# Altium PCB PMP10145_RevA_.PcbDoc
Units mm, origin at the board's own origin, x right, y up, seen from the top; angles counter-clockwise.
Board outline 111 x 62 mm, 2 copper layers (Top Layer, Bottom Layer), stack 1.57 mm thick; 72 components, 120 nets, 175 pads, 38 vias.
Unrouted connection lines stored in the file: 1.
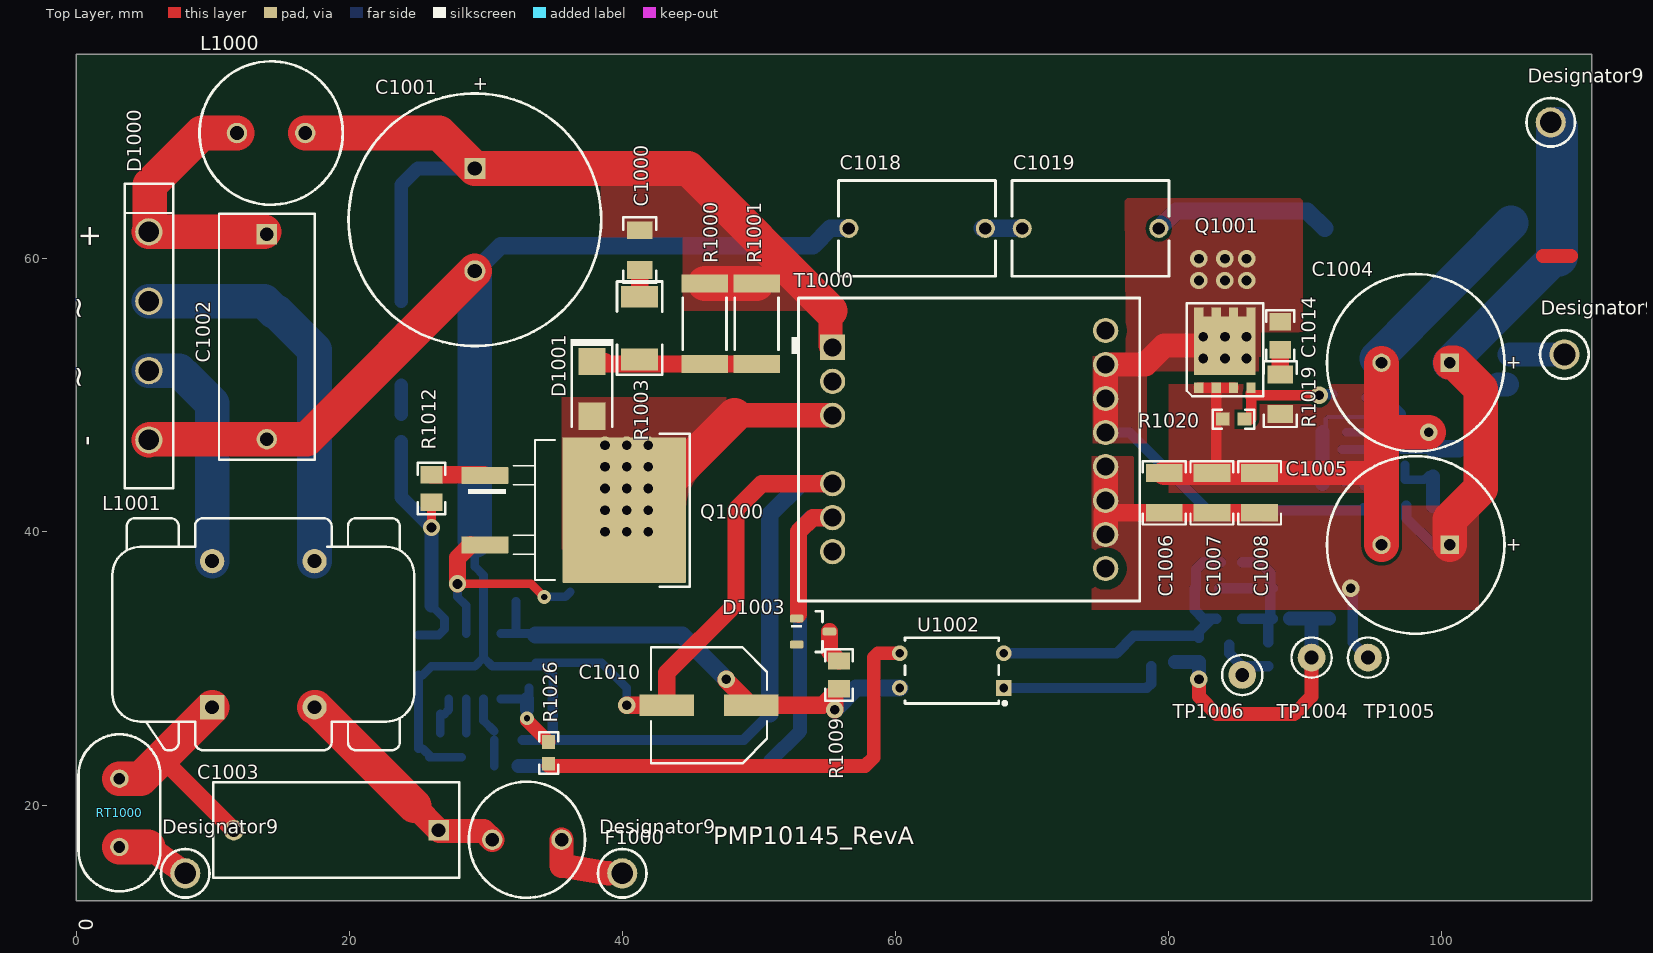
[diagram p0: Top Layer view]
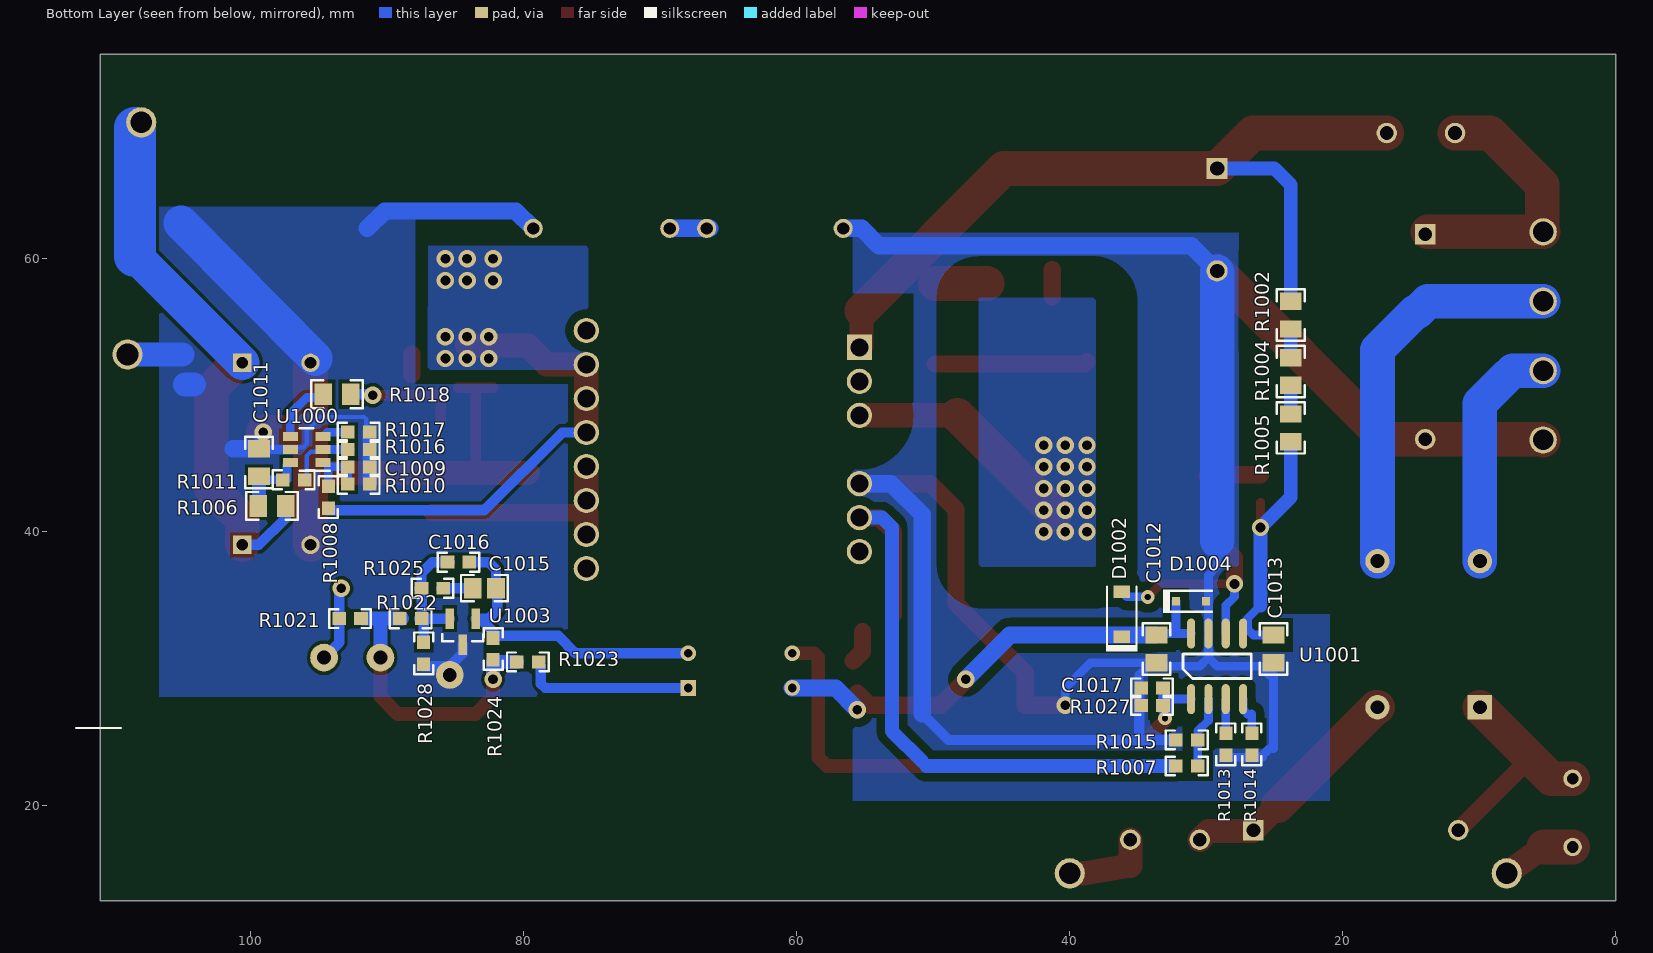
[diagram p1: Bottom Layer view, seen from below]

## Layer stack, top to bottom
Top Solder: solder mask 0.01, Solder Resist, Dk 3.5
Top Layer: signal copper 0.035
Dielectric 1: core 1.5, FR-4, Dk 4.2
Bottom Layer: signal copper 0.035
Bottom Solder: solder mask 0.01, Solder Resist, Dk 3.5

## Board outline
0,13 111,13 111,75 0,75

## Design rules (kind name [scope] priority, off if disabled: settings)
AssemblyTestPointUsage [All] p1 off:
AssemblyTestpoint [All] p1 off: testpointundercomponent=TRUE minsize=1.016 maxsize=2.54 preferedsize=1.524 minholesize=0 maxholesize=1.016 preferedholesize=0.813 testpointgrid=0.025 usegrid=TRUE gridtolerance=0 allowsidetop=TRUE allowsidebottom=TRUE
Clearance "PGND C1000" [InNet('PGND') vs InNet('NetC1000_1')] p1: gap=3.048
Clearance "PGND D1001" [InNet('PGND') vs InNet('NetD1001_2')] p2: gap=3.048
Clearance GND [InNet('GND')] p3: gap=0.254
Clearance "N L1" [InNet('V_N') vs InNet('V_L1')] p4: gap=3.048
Clearance Clearance_polygon [INPOLYGON] p5: gap=0.635
Clearance "PGND Vin" [InNet('PGND') vs InNet('NetC1000_1')] p6: gap=3.048
Clearance "PGND ALL" [InNet('PGND')] p7: gap=0.635
DiffPairsRouting [All] p1: maxlimit=0.254 minlimit=0.254 mostfreqgap=0.254 toplayer_minwidth=0.254 toplayer_maxwidth=3.048 toplayer_prefwidth=0.381 bottomlayer_minwidth=0.254 bottomlayer_maxwidth=3.048 bottomlayer_prefwidth=0.381 maxuncoupledlength=12.7
FabricationTestPointUsage [All] p1 off: valid=0 allowmultiple=FALSE
FabricationTestpoint [All] p1 off: side=3 testpointundercomponent=TRUE minsize=1.016 maxsize=2.54 preferedsize=1.524 minholesize=0 maxholesize=1.016 preferedholesize=0.813 testpointgrid=0.025 allowsidetop=TRUE allowsidebottom=TRUE usegrid=TRUE gridtolerance=0
Height [All] p1: minheight=0 maxheight=50.8 prefheight=12.7
HoleSize [All] p1: absolutevalues=TRUE maxlimit=25.4 minlimit=0.025 maxpercent=80.000 minpercent=20.000
MinimumSolderMaskSliver [All] p1: minsoldermaskwidth=0.025
PasteMaskExpansion [All] p1: expansion=-0.025
PlaneClearance [All] p1: clearance=0.279
PlaneConnect [All] p1: planeconnectstyle=Relief reliefexpansion=0.152 reliefentries=4 reliefconductorwidth=0.254 reliefairgap=0.178
PolygonConnect PolygonConnect_VIA [ISVIA] p1: connectstyle=Direct reliefconductorwidth=0.254 reliefentries=4 polygonreliefangle="90 Angle" airgapwidth=0.254
PolygonConnect [All] p2: connectstyle=Direct reliefconductorwidth=0.254 reliefentries=4 polygonreliefangle="90 Angle" airgapwidth=0.254
RoomDefinition V3 [InComponentClass('V3')] p1: confinementstyle=ConfineIn formatcopy=TRUE lockcomponents=FALSE outline -255.27,-245.872 -204.47,-245.872 -204.47,-220.472 -255.27,-220.472
RoutingVias [All] p1: holewidth=0.4 width=0.705 viastyle="Through Hole" minholewidth=0.2 minwidth=0.505 maxholewidth=1 maxwidth=1.991
SilkToBoardRegionClearance [All] p1 off:
SilkToSilkClearance [All] p1: silktosilkclearance=0.102
SilkToSolderMaskClearance SilkscreenOverComponentPads [IsPad] p1: minsilkscreentomaskgap=0.051 clearancetoexposedcopper=TRUE
SolderMaskExpansion SolderMaskExpansion_qfn48 [HasFootprint('QFN48#0.5')] p1: expansion=0.051
SolderMaskExpansion SolderMaskExpansion_32QN2 [(HasFootprint('32QN2'))] p2: expansion=0.051
SolderMaskExpansion [All] p3: expansion=0.051
UnpouredPolygon [All] p1: allowunpoured=FALSE
Width Width_ekran [InNet('GND')] p1: maxlimit=3.048 minlimit=0.127 preferedwidth=0.254
Width [All] p2: maxlimit=3.048 minlimit=0.127 preferedwidth=0.254
15 further rules are at their usual default settings.

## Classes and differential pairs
net class V_L[3..1]: V_L1 V_L2 V_L3
channel class V_PHASE_IN: V1 V2 V3
channel class I_CT_IN: I1 I2 I3 I4
net class V_PAHSE[3..1]: V_PAHSE1 V_PAHSE2 V_PAHSE3
net class I_CT_P[4..1]: I_CT_P1 I_CT_P2 I_CT_P3 I_CT_P4
net class I_CT_N[4..1]: I_CT_N1 I_CT_N2 I_CT_N3 I_CT_N4
component class Main: C20 TP8 TP12 U4
differential pair RS1: +RS1_P -RS1_N
differential pair RS: +RS_P -RS_N

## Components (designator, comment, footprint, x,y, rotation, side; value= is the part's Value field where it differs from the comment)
C1000 "C3216X7R2J472K" 1206 41.275,60.642 r270 top
C1001 "EKXG451ELL680MMN3S" KXG_1800x3150 29.21,62.865 r270 top
C1002 "B32922C3224K" B32922_12.5mm 13.97,54.292 r270 top
C1003 "B32922C3224K" B32922_12.5mm 19.05,18.161 r180 top
C1004 "EKZE350ELL681MK20S" KZE_1250x2000 98.108,52.387 r180 top
C1005 "EKZE350ELL681MK20S" KZE_1250x2000 98.108,39.052 r180 top
C1006 "GRM32ER71C226ME18L" 1210 79.692,42.862 r90 top
C1007 "GRM32ER71C226ME18L" 1210 83.185,42.862 r90 top
C1008 "GRM32ER71C226ME18L" 1210 86.677,42.862 r90 top
C1009 "Used in BOM report" 0603 92.075,44.767 r180 bottom
C1010 "EEE-FC1V470P" SM_RADIAL_E 46.355,27.305 r180 top
C1011 "GRM219R71E105KA88D" 0805_HV 99.377,45.085 r90 bottom
C1012 "08055C104JAT2A" 0805_HV 33.655,31.432 r270 bottom
C1013 "08055C104JAT2A" 0805_HV 25.082,31.432 r270 bottom
C1014 "GRM2165C2A222JA01D" 0805_HV 88.186,54.372 r270 top
C1015 "Used in BOM report" 0805 82.867,35.877 r180 bottom
C1016 "C0603C103J5RACTU" 0603 84.772,37.782 r180 bottom
C1017 "06035A101JAT2A" 0603 33.972,28.575 r0 bottom
C1018 "ECKANA222ME" CD_1150x700x1550 61.595,62.23 r180 top
C1019 "ECKANA222ME" CD_1150x700x1550 74.295,62.23 r180 top
D1000 "GBU4J" GBU 5.334,54.356 r270 top
D1001 "MURA160T3G" SMA 37.782,50.482 r270 top
D1002 "MBR0540T1G" SOD-123 36.195,33.972 r90 bottom
D1003 "BAS21-7-F" SOT-23 53.975,32.703 r0 top
D1004 "MMSZ5251BS-7-F" sod-323 31.115,34.925 r180 bottom
Designator9 "Comment" Keystone5011 109,53 r0 top
Designator9 "Comment" Keystone5010 108,70 r0 top
Designator9 "Comment" Keystone5010 8,15 r0 top
Designator9 "Comment" Keystone5010 40,15 r0 top
F1000 "37212000001" FUSE_372 33.02,17.462 r0 top
L1000 "7447480331" WE_TI_1014 14.287,69.215 r0 top
L1001 "744823210" IND_WE-CMB_M 13.716,32.512 r90 top
Q1000 "STB8N65M5" DDPAK 36.195,41.593 r0 top
Q1001 "CSD19531Q5A" TRANS_NexFET_Q5A 84.138,53.34 r90 top
R1000 "CRCW2512100KJNEG" 2512 46.038,55.245 r90 top
R1001 "CRCW2512100KJNEG" 2512 49.847,55.245 r90 top
R1002 "CRCW08051M00FKEA" 0805_HV 23.812,55.88 r90 bottom
R1003 "CRCW201047R0JNEF" 2010 41.275,54.927 r90 top
R1004 "CRCW08051M00FKEA" 0805_HV 23.812,51.752 r90 bottom
R1005 "CRCW08051M00FKEA" 0805_HV 23.812,47.625 r90 bottom
R1006 "CRCW080510R0JNEA" 0805_HV 98.425,41.91 r180 bottom
R1007 "CRCW0603191KFKEA" 0603 31.432,22.86 r0 bottom
R1008 "Used in BOM report" 0603 94.297,42.545 r90 bottom
R1009 "CRCW080510R0JNEA" 0805_HV 55.88,29.527 r90 top
R1010 "Used in BOM report" 0603 92.075,43.497 r0 bottom
R1011 "Used in BOM report" 0603 96.837,43.815 r0 bottom
R1012 "CRCW080510R0JNEA" 0805_HV 26.035,43.18 r270 top
R1013 "CRCW060333K2FKEA" 0603 28.575,24.447 r90 bottom
R1014 "CRCW0603100KFKEA" 0603 26.67,24.447 r90 bottom
R1015 "CRCW060356K2FKEA" 0603 31.432,24.765 r180 bottom
R1016 "Used in BOM report" 0603 92.075,46.038 r0 bottom
R1017 "Used in BOM report" 0603 92.075,47.307 r0 bottom
R1018 "CRCW080510R0JNEA" 0805_HV 93.662,50.086 r180 bottom
R1019 "CRCW120610R0JNEA" 1206 88.186,50.086 r90 top
R1020 "Used in BOM report" 0603 84.772,48.26 r0 top
R1021 "CRCW060349R9FKEA" 0603 92.71,33.655 r180 bottom
R1022 "CRCW0603100KFKEA" 0603 88.265,33.655 r0 bottom
R1023 "CRCW06031K00FKEA" 0603 79.692,30.48 r0 bottom
R1024 "CRCW06034K99FKEA" 0603 82.233,31.432 r270 bottom
R1025 "Used in BOM report" 0603 86.677,35.877 r0 bottom
R1026 "CRCW060320K0FKEA" 0603 34.608,23.812 r270 top
R1027 "CRCW0603100KFKEA" 0603 33.972,27.305 r180 bottom
R1028 "CRCW060338K3FKEA" 0603 87.312,31.115 r90 bottom
RT1000 "B57236S0100M000" THERM_B57236S0 3.175,19.431 r90 top
T1000 "750315431" Wurth_750315431 65.405,46.038 r0 top
TP1004 "5000" Keystone5000 90.487,30.797 r90 top
TP1005 "5000" Keystone5000 94.615,30.797 r90 top
TP1006 "5001" Keystone5001 85.407,29.527 r90 top
U1000 "UCC24630DBV" DBV0006A_N 95.885,46.038 r0 bottom
U1001 "UCC28610D" D0008A_N 29.21,30.162 r90 bottom
U1002 "FOD817A" DIP-4 64.135,29.845 r180 top
U1003 "TL431AIDBZ" DBZ0003A_N 84.455,32.703 r270 bottom

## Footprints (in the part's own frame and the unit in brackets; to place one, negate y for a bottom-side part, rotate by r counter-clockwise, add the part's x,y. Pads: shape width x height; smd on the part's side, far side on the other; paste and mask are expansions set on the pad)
0603 [mm] "0603 from SM-752 data"
  rect 1x0.95 smd: 1(-0.8,0) 2(0.8,0)
  silkscreen extent -1.52,-0.69 1.52,0.69, body extent -0.87,-0.47 0.87,0.47, height 0.85
0805 [mm] "0805 from SM-752 data"
  rect 1.3x1.5 smd: 1(-0.85,0) 2(0.85,0)
  silkscreen extent -1.72,-0.97 1.72,0.97, body extent -1.1,-0.72 1.1,0.72, height 1.1
0805_HV [mil] "0805 with 30mil clearance between pads"
  rect 50x63 smd: 1(-40,0) 2(40,0)
  silkscreen extent -74,-40 74,40, body extent -43,-29 43,29, height 43
1206 [mm] "1206 from SM-752 data"
  rect 1.3x1.85 smd: 1(-1.45,0) 2(1.45,0)
  silkscreen extent -2.4,-1.21 2.4,1.21, body extent -1.7,-0.9 1.7,0.9, height 1.35
1210 [mm] "1210 from SM-752 data"
  rect 1.3x2.7 smd: 1(-1.45,0) 2(1.45,0)
  silkscreen extent -2.32,-1.57 2.32,1.57, body extent -1.7,-1.35 1.7,1.35, height 1.35
2010 [mm] "Chip Capacitor, Body 5.08x2.54mm, IPC Medium Density"
  rect 1.6x2.7 smd: 1(-2.3,0) 2(2.3,0)
  silkscreen extent -3.42,-1.65 3.42,1.65, body extent -2.73,-1.45 2.73,1.45, height 1.66
2512 [mm] "Chip Resistor, Body 6.3x3.2mm, IPC Medium Density"
  rect 1.3x3.4 smd: 1(-2.95,0) 2(2.95,0)
  silkscreen extent -1.9,-1.6 1.9,1.6, body extent -3.22,-1.67 3.22,1.67, height 0.71
B32922_12.5mm [mm] "Epcos film capacitors, 15mm spacing"
  rect 1.5x1.5 hole 1: 1(-7.5,0)
  round 1.5 hole 1: 2(7.5,0)
  silkscreen extent -9,-3.5 9,3.5, body extent -9,-3.5 9,3.5, height 12.5
CD_1150x700x1550 [mm] "TH, 2-Leads, Body 11.5x7mm, Pin Spacing 10mm"
  round 1.4 hole 0.9: 1(-5,0) 2(5,0)
  silkscreen extent -5.75,-3.5 5.75,3.5, body extent -5.73,-3.5 5.73,3.5, height 15.49
D0008A_N [mm] "SOIC, 8-Leads, Body 4.9x3.9mm, Pitch 1.27mm, IPC Medium Density"
  oval 2.2x0.6 smd: 1(-2.4,1.905) 2(-2.4,0.635) 3(-2.4,-0.635) 4(-2.4,-1.905) 5(2.4,-1.905) 6(2.4,-0.635) 7(2.4,0.635) 8(2.4,1.905)
  silkscreen extent -0.9,-2.5 0.9,2.5, body extent -3,-2.45 3,2.45, height 1.63
DBV0006A_N [mm] "SOT23, 6-Leads, Body 2.9x1.6mm, Pitch 0.95mm, Lead Span 2.8mm, IPC Medium Density"
  rect 1.1x0.65 smd: 1(-1.2,0.95) 2(-1.2,0) 3(-1.2,-0.95) 4(1.2,-0.95) 5(1.2,0) 6(1.2,0.95)
  silkscreen extent -1.68,-1.55 0.5,1.55, body extent -1.42,-1.46 1.42,1.46, height 1.11
DBZ0003A_N [mm] "SOT23, 3-Leads, Body 2.9x1.3mm, Pitch 0.95mm, Lead Span 2.4mm, IPC Medium Density"
  rect 1.5x0.6 smd: 1(-0.95,0.95) 2(-0.95,-0.95) 3(0.95,0)
  silkscreen extent 0.2,-1.5 0.7,1.5, body extent -1.26,-1.46 1.26,1.46, height 0.96
DDPAK [mil] "D2-PAK, 3-Pads, Body 9.7x10.4mm (max), TO-263AB, using Vishay Silionix recommended pad sizes"
  rrect8% 135x49.49 smd: 1(-246.06,100) 3(-246.06,-100)
  rrect1% 355x420 smd paste-181.1: 4(155.51,0)
  silkscreen extent -295,-220 344,220, body extent -295,-202 324,202, height 180
DIP-4 [mm] "DIP, 4-Leads, Body 6.86x4.83mm, Pitch 2.54mm"
  rect 1.15x1.15 hole 0.65: 1(-3.81,1.27)
  round 1.15 hole 0.65: 2(-3.81,-1.27) 3(3.81,-1.27) 4(3.81,1.27)
  silkscreen extent -4,-2.41 3.43,2.52, body extent -4.02,-2.41 4.02,2.41, height 5.59
FUSE_372 [mm] "LITTELFUSE"
  round 1.5 hole 1: 1(-2.54,0) 2(2.54,0)
  silkscreen extent -4.25,-4.25 4.25,4.25, body extent -4.26,-4.26 4.26,4.26, height 8
GBU [mm] "Comchip / Diodes Inc diode bridge"
  round 2 hole 1.5: 1(-7.62,0) 2(-2.54,0) 3(2.54,0) 4(7.62,0)
  silkscreen extent -11.15,-1.78 11.15,1.78, body extent -11.15,-1.76 11.15,1.8, height 21.55
IND_WE-CMB_M [mil] "Wurth"
  rect 70x70 hole 40: 1(-210.63,147.64)
  round 70 hole 40: 2(210.63,147.64) 3(210.63,-147.64) 4(-210.63,-147.64)
  silkscreen extent -335,-435 335,435, body extent -335,-394 335,394, height 1044
Keystone5000 [mil] "For Keystone 500x miniature loop terminals"
  round 80 hole 40: 1(0,0)
  silkscreen extent -58,-58 58,58, body extent -49,-49 49,49, height 182
Keystone5001 [mil] "For Keystone 500x miniature loop terminals"
  round 80 hole 40: 1(0,0)
  silkscreen extent -58,-58 58,58, body extent -49,-49 49,49, height 182
Keystone5010 [mil] "Keystone Multipurpose loops"
  round 87 hole 63: 1(0,0)
  silkscreen extent -70,-70 70,70, body extent -63,-63 63,62, height 319
Keystone5011 [mil] "Keystone Multipurpose loops"
  round 87 hole 63: 1(0,0)
  silkscreen extent -70,-70 70,70, body extent -63,-63 63,62, height 319
KXG_1800x3150 [mm] "TH, 2-Leads, Dia 18mm, Pin Spacing 7.5mm"
  rect 1.55x1.55 hole 1.05: 1(-3.75,0)
  round 1.55 hole 1.05: 2(3.75,0)
  silkscreen extent -9.25,-9.25 9.25,9.25, body extent -9.18,-9.33 9.22,9.14, height 33.01
KZE_1250x2000 [mm] "TH, 2-Leads, Dia 12.5mm, Lead Sapcing 5mm"
  rect 1.35x1.35 hole 0.85: 1(-2.5,0)
  round 1.35 hole 0.85: 2(2.5,0)
  silkscreen extent -6.5,-6.5 6.5,6.5, body extent -6.45,-6.49 6.49,6.49, height 21.5
SM_RADIAL_E [mm] "8 x 6.2mm:  Panasonic E"
  rect 4x1.6 smd: 1(-3.1,0) 2(3.1,0)
  silkscreen extent -4.25,-4.25 4.25,4.25, body extent -4.26,-4.26 4.26,4.26, height 6.5
SMA [mm] "Molded Diode, 2-Leads, Body 4.3x2.6mm, IPC Medium Density, based on OnSemi component dimensions and land pattern"
  rect 2x2 smd: 1(-2,0) 2(2,0)
  silkscreen extent -3.66,-1.57 2.79,1.57, body extent -2.6,-1.3 2.6,1.3, height 2.42
SOD-123 [mm] "On Semi recommended land pattern"
  rect 0.915x1.22 smd: 1(-1.637,0) 2(1.637,0)
  silkscreen extent -2.74,-1.17 2.03,1.17, body extent -1.93,-0.9 1.93,0.9, height 1.35
sod-323 [mm] "NXP recommended land pattern"
  rect 0.6x0.6 smd paste-0.05: 1(-1.1,0) 2(1.1,0)
  silkscreen extent -2.06,-0.86 1.53,0.86, body extent -1.3,-0.67 1.3,0.68, height 1.1
SOT-23 [mm] "SOT23, 3-Leads, Body 2.9x1.3mm, Pitch 0.95mm, Lead Span 2.5mm, IPC Medium Density"
  rrect50% 1x0.6 smd: 1(-1.2,0.95) 2(-1.2,-0.95) 3(1.2,0)
  silkscreen extent -1.63,-1.5 0.7,1.5, body extent -1.16,-1.45 1.21,1.45, height 1
THERM_B57236S0 [mm] "EPCOS"
  round 1.35 hole 0.85: 1(-2.5,0) 2(2.5,0)
  silkscreen extent -5.75,-3 5.75,3, body extent -5.75,-3 5.7,3, height 15.99
TRANS_NexFET_Q5A [mm] "TI recommended land pattern (nominal) M0139-01"
  rect 0.75x0.675 smd paste-0.1 mask+0.051: 1(-2.776,1.917) 2(-2.776,0.639) 3(-2.776,-0.639) 4(-2.776,-1.917)
  rect 0.655x0.675 smd paste-0.1 mask+0.051: 5(2.776,-1.917) 6(2.776,-0.639) 7(2.776,0.639) 8(2.776,1.917)
  rect 4.295x4.51 smd paste-2.2 mask+0.051: 9(0.301,0)
  silkscreen extent -3.4,-2.8 3.4,2.8, body extent -3.05,-2.5 3.05,2.5, height 1.11
WE_TI_1014 [mm] "TH, 2-Leads, Dia 10.5mm, Pitch 1mm"
  round 1.5 hole 1: 1(-2.5,0) 2(2.5,0)
  silkscreen extent -5.25,-5.25 5.25,5.25, body extent -5.26,-5.26 5.26,5.26, height 14.5
Wurth_750315431 [mm] "TH, 14-Leads, Body 25x22.2mm, Pitch 2.49mm"
  rect 1.85x1.85 hole 1.32: 1(-10,7.48)
  round 1.85 hole 1.32: 2(-10,4.99) 3(-10,2.5) 4(-10,-2.5) 5(-10,-4.99) 6(-10,-7.48) 7(10,-8.715) 8(10,-6.225) 9(10,-3.735) 10(10,-1.245) 11(10,1.245) 12(10,3.735) 13(10,6.225) 14(10,8.715)
  silkscreen extent -13,-11.1 12.5,11.1, body extent -12.5,-11.1 12.5,11.1, height 16

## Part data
C1000: "CAP, CERM, 4700 pF, 630 V, +/- 10%, X7R, 1206"
C1001: "CAP, AL, 68 µF, 450 V, +/- 20%,  ohm, TH"
C1002 C1003: "CAP, Film, 0.22 µF, 630 V, +/- 10%, TH"
C1004 C1005: "CAP, AL, 680 µF, 35 V, +/- 20%, 0.021 ohm, TH"
C1006 C1007 C1008: "CAP, CERM, 22 µF, 16 V, +/- 20%, X7R, 1210"
C1009 C1015: library part Capacitor, "CAP, CERM, xxxF, xxV, [TempCo], xx%, [PackageReference]"
C1010: "CAP, AL, 47 µF, 35 V, +/- 20%, 0.4 ohm, SMD"
C1011: "CAP, CERM, 1 µF, 25 V, +/- 10%, X7R, 0805"
C1012 C1013: "CAP, CERM, 0.1 µF, 50 V, +/- 5%, X7R, 0805"
C1014: "CAP, CERM, 2200 pF, 100 V, +/- 5%, C0G/NP0, 0805"
C1016: "CAP, CERM, 0.01 µF, 50 V, +/- 5%, X7R, 0603"
C1017: "CAP, CERM, 100 pF, 50 V, +/- 5%, C0G/NP0, 0603"
C1018 C1019: library part CD12-E2GA222MYGS, "CAP, CERM, 2200 pF, 250 V, +/- 20%, E, TH, 2-Leads, Body 11.5x7mm, Pin Spacing 10mm"
D1000: library part GBU4K-E3/45, "Diode, Switching-Bridge, 600 V"
D1001: "Diode, Ultrafast, 600 V, 1 A, SMA"
D1002: "Diode, Schottky, 40 V, 0.5 A, SOD-123"
D1003: "Diode, Switching, 200 V, 0.2 A, SOT-23"
D1004: "Diode, Zener, 22 V, 200 mW, SOD-323"
F1000: "Fuse, 2 A, 250 V, TH"
L1000: "Inductor, Wirewound, Ferrite, 330 µH, 1.4 A, 0.3 ohm, TH"
L1001: "Coupled inductor, 10 mH, 2 A, 0.125 ohm, +/- 30%, TH"
Q1000: "MOSFET, N-CH, 710 V, 7 A, DDPAK"
Q1001: "MOSFET, N-CH, 100 V, 16 A, SON 5x6mm"
R1000 R1001: "RES, 100 k, 5%, 1 W, 2512"
R1002 R1004 R1005: "RES, 1.00 M, 1%, 0.125 W, 0805"
R1003: "RES, 47, 5%, 0.75 W, 2010"
R1006 R1009 R1012 R1018: "RES, 10, 5%, 0.125 W, 0805"
R1007: "RES, 191 k, 1%, 0.1 W, 0603"
R1008 R1010 R1011 R1016 R1017 R1020 R1025: library part Resistor, "RES, xxx ohm, x%, xW, [PackageReference]"
R1013: "RES, 33.2 k, 1%, 0.1 W, 0603"
R1014 R1022 R1027: "RES, 100 k, 1%, 0.1 W, 0603"
R1015: "RES, 56.2 k, 1%, 0.1 W, 0603"
R1019: "RES, 10, 5%, 0.25 W, 1206"
R1021: "RES, 49.9, 1%, 0.1 W, 0603"
R1023: "RES, 1.00 k, 1%, 0.1 W, 0603"
R1024: "RES, 4.99 k, 1%, 0.1 W, 0603"
R1026: "RES, 20.0 k, 1%, 0.1 W, 0603"
R1028: "RES, 38.3 k, 1%, 0.1 W, 0603"
RT1000: "Thermistor NTC, 10 ohm, 20%, Disc_11.5mmx6mm"
T1000: "Transformer, 150uH, TH"
TP1004 TP1005: "Test Point, Miniature, Red, TH"
TP1006: "Test Point, Miniature, Black, TH"
U1000: "SYNCRONOUS RECTIFIER CONTROLLER WITH LOW POWER STANDBY, DBV0006A"
U1001: "Green-Mode Flyback Power Supply Controller with Discontinuous Current Control, -40 to +125 degC, 8-pin SOIC (D), Green (RoHS & no Sb/Br)"
U1002: "High Operating Temperature Phototransistor Optocoupler, DIP-4"
U1003: "PRECISION PROGRAMMABLE REFERENCE, DBZ0003A"

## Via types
v1: diameter 1.27, hole 0.711, Top Layer to Bottom Layer, 36 vias
v2: diameter 1.016, hole 0.457, Top Layer to Bottom Layer, 2 vias

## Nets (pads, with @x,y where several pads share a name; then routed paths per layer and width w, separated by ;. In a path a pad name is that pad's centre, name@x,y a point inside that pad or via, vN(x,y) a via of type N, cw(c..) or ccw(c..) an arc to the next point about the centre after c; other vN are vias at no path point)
+3V3: 
+5V: 
+9V: C1004.1 C1005.1 C1006.1 C1007.1 C1008.1 R1006.2 R1021.1 T1000.8 T1000.9 T1000.10 TP1005.1 | length 63.8
  Top Layer w1.016: 107.442,60.198 109.474,60.198
  Top Layer w1.27: T1000.9@75.385,41.413 75.405,41.413 C1006.1 C1007.1 C1008.1
  Top Layer w1.778: T1000.8@75.405,39.845 T1000.9@75.405,41.413 ; T1000.9 T1000.10
  Top Layer w2.54: C1005.1 100.608,40.918 102.87,43.18 102.87,50.482 100.965,52.387 C1004.1@100.647,52.387
  Bottom Layer w0.762: v1(93.345,35.877) 93.51,35.712 R1021.1 93.51,31.902 TP1005.1 ; R1006.2 97.409,41.021 99.377,39.052 C1005.1
  Bottom Layer w2.54: C1004.1 108.267,60.047 108.267,60.325
  Bottom Layer w3.048: 108.458,60.198 108.458,69.596
AGND: 
EM_IRQ0: 
EM_SCL: 
EM_SDA: 
EXT_MB_RTS: 
EXT_MB_RXD: 
EXT_MB_TXD: 
GND: C1004.2 C1005.2 C1006.2 C1007.2 C1008.2 C1009.2 C1011.2 C1019.1 Designator9.1@109,53 Q1001.1 Q1001.2 Q1001.3 R1010.1 R1016.1 R1017.1 R1019.1 R1020.1 R1028.1 TP1006.1 U1000.5 U1003.3 | length 92.5
  Top Layer w0.762: Q1001.1 Q1001.2 ; C1007.2@83.498,44.626 Q1001.2 ; Q1001.3 Q1001.2
  Top Layer w1.778: C1006.2 C1007.2 C1008.2 94.16,44.312
  Top Layer w2.54: 95.567,47.307 95.607,47.307 ; C1005.2 95.607,47.307 ; C1004.2@95.607,52.348 95.607,47.307 ; v1(99.06,47.307) 95.607,47.307
  Bottom Layer w0.305: R1017.1@91.519,47.625 91.519,48.26 91.678,48.419 94.853,48.419 95.885,47.387 95.885,46.434 96.123,46.196 U1000.5@97.085,46.196
  Bottom Layer w0.635: U1000.5 C1011.2@99.377,46.038 ; v1(99.06,47.307) 99.377,46.99 C1011.2
  Bottom Layer w0.762: U1003.3 84.455,31.115 85.407,30.162 R1028.1@87.312,30.162
  Bottom Layer w1.016: R1010.1@91.275,43.504 R1016.1 R1017.1
  Bottom Layer w1.27: C1019.1 80.565,63.5 90.17,63.5 91.44,62.23 ; C1011.2 101.267,46.101 101.282,46.117
  Bottom Layer w1.778: 104.14,50.8 104.775,50.8 ; 105,53 Designator9.1@109,53
  Bottom Layer w2.54: C1004.2@95.25,52.705 95.269,52.724 105.093,62.627
I_CT_N1: 
I_CT_N2: 
I_CT_N3: 
I_CT_N4: 
I_CT_P1: 
I_CT_P2: 
I_CT_P3: 
I_CT_P4: 
MB_GND: 
NetC1_2: 
NetC3_2: 
NetC5_2: 
NetC8_2: 
NetC9_2: 
NetC10_2: 
NetC11_2: 
NetC13_I1_2: 
NetC13_I2_2: 
NetC13_I3_2: 
NetC13_I4_2: 
NetC15_I1_1: 
NetC15_I2_1: 
NetC15_I3_1: 
NetC15_I4_1: 
NetC21_2: 
NetC28_2: 
NetC32_1: 
NetC32_2: 
NetC1000_1: C1000.1 C1001.1 L1000.2 R1000.2 R1001.2 R1002.2 T1000.1 | length 64.6
  Top Layer w1.778: T1000.1@55.245,53.657 55.245,56.197
  Top Layer w2.54: L1000.2 26.61,69.215 C1001.1 44.827,66.615 55.245,56.197 ; R1000.2 R1001.2
  Bottom Layer w1.016: R1002.2 23.812,65.405 25.023,66.615 C1001.1
NetC1000_2: C1000.2 R1003.2 | length 2
  Top Layer w1.27: R1003.2 C1000.2
NetC1002_1: C1002.1 D1000.1 L1000.1 | length 19.9
  Top Layer w2.54: L1000.1 9.207,69.215 5.397,65.405 5.397,62.039 D1000.1 C1002.1@13.787,61.976
NetC1003_1: C1003.1 F1000.1 L1001.4 | length 17
  Top Layer w1.778: 24.765,19.946 C1003.1 26.614,18.098 29.845,18.098 F1000.1
  Top Layer w2.54: L1001.4 17.549,27.162 24.765,19.946
NetC1003_2: C1003.2 L1001.1 RT1000.2 | length 16.3
  Top Layer w1.27: 6.349,23.362 C1003.2
  Top Layer w2.54: RT1000.2 4.735,21.931 L1001.1
NetC1009_1: C1009.1 R1008.2 R1010.2 U1000.1 | length 3.8
  Bottom Layer w0.635: R1010.2@92.875,43.65 C1009.1 ; C1009.1@93.027,44.767 94.297,44.767 R1008.2
NetC1010_1: C1010.1 C1012.1 D1002.1 D1004.1 R1009.1 U1001.8 U1002.4 | length 35.9
  Top Layer w1.27: v1(47.625,29.21) 47.625,29.135 C1010.1 54.673,27.305 55.562,28.194 v1(55.562,26.987)
  Bottom Layer w0.635: U1001.8 33.541,32.563 C1012.1 ; 32.215,32.676 D1004.1
  Bottom Layer w1.27: C1012.1 44.387,32.448 v1(47.625,29.21) ; v1(55.562,26.987) 57.15,28.575 U1002.4
NetC1011_1: C1011.1 R1006.1 R1011.2 U1000.6 | length 5.1
  Bottom Layer w0.635: U1000.6@97.32,44.932 97.32,43.815 R1011.2 98.742,43.815 C1011.1@99.06,44.133
  Bottom Layer w1.016: R1006.1@99.377,41.91 C1011.1
NetC1013_1: C1013.1 R1005.1 R1012.2 U1001.5 | length 19
  Top Layer w0.635: v1(26.035,40.322) R1012.2
  Bottom Layer w0.635: C1013.1 26.556,32.448 26.987,32.88 26.987,33.655 26.035,34.608
  Bottom Layer w1.016: R1005.1 23.812,42.545 v1(26.035,40.322) 26.035,34.608
NetC1014_1: C1014.1 Q1001.5 Q1001.6 Q1001.7 Q1001.8 Q1001.9 R1008.1 T1000.11 T1000.12 T1000.13 | length 35.7
  Top Layer w1.778: T1000.11 T1000.12 T1000.13@75.405,52.228 ; T1000.13 78.298,52.263 79.692,53.657 84.121,53.657 Q1001.9
  Bottom Layer w0.762: T1000.11 77.177,47.283 82.867,41.593 R1008.1@94.297,41.593 ; R1008.1@94.139,41.593 R1008.1@94.297,41.751
  other v1: 82.55,52.705 84.138,52.705 85.725,52.705 82.55,54.292 84.138,54.292 85.725,54.292 82.233,58.42 84.138,58.42 85.725,58.42 82.233,60.008 84.138,60.008 85.725,60.008
NetC1014_2: C1014.2 R1019.2 | length 1.5
  Top Layer w1.27: R1019.2 C1014.2@88.186,53.023
NetC1015_1: C1015.1 R1025.1 | length 2.3
  Bottom Layer w0.762: C1015.1 R1025.1 R1025.1@86.042,35.877
NetC1015_2: C1015.2 C1016.2 R1024.1 U1002.2 U1003.1 | length 23.5
  Bottom Layer w0.762: U1002.2 76.2,31.115 77.47,32.385 R1024.1@82.233,32.385 ; C1015.2@81.915,35.877 81.915,34.29 82.553,33.652 83.182,33.652 ; C1015.2 82.018,37.25 82.55,37.782 C1016.2@83.82,37.782 ; R1024.1 R1024.1@82.233,32.385 ; U1003.1 83.182,33.652 ; R1024.1@82.233,32.385 82.233,32.703 83.182,33.652
NetC1016_1: C1016.1 R1022.1 R1025.2 R1028.2 U1003.2 | length 9.6
  Bottom Layer w0.762: U1003.2 R1022.1@87.312,33.652 ; C1016.1@85.407,37.782 C1016.1 86.677,37.782 87.477,36.983 R1025.2 ; R1028.2 R1022.1@87.312,33.652 ; R1022.1@87.312,33.655 R1022.1@87.312,33.652 ; R1022.1@87.465,33.652 R1022.1@87.627,33.652 ; R1022.1 87.465,35.712 R1025.2@87.63,35.877
NetC1017_1: C1017.1 R1026.1 R1027.2 U1001.1 | length 6.6
  Top Layer w1.016: v2@33.02,26.2 R1026.1
  Bottom Layer w0.635: U1001.1 32.715,27.762 33.02,27.458 R1027.2 C1017.1
  Bottom Layer w1.016: R1027.2@33.02,26.987 33.02,27.458 33.02,27.787
  other v2: 33.02,26.352
NetC1018_1: C1018.1 C1019.2 | length 2.9
  Bottom Layer w1.27: C1018.1@66.358,62.23 C1018.1 C1019.2
NetD1_I1_1: 
NetD1_I1_2: 
NetD1_I2_1: 
NetD1_I2_2: 
NetD1_I3_1: 
NetD1_I3_2: 
NetD1_I4_1: 
NetD1_I4_2: 
NetD3_1: 
NetD4_1: 
NetD1000_2: D1000.2 L1001.3 | length 29.1
  Bottom Layer w2.54: D1000.2 13.767,56.896 14.536,56.128 14.675,56.128 17.462,53.34 L1001.3@17.462,37.865
NetD1000_3: D1000.3 L1001.2 | length 16.6
  Bottom Layer w2.54: D1000.3 7.556,51.816 ; 7.938,51.435 9.966,49.407 L1001.2
NetD1001_1: D1001.1 R1000.1 R1001.1 R1003.1 | length 11.2
  Top Layer w1.27: D1001.1@38.735,52.482 38.922,52.295 R1000.1 R1001.1
NetD1001_2: D1001.2 Q1000.4 T1000.3 | length 17.4
  Top Layer w1.778: 48.22,48.538 T1000.3
  Top Layer w2.54: Q1000.4@41.097,41.275 41.097,41.415 48.22,48.538
  other v1: 38.735,40.005 40.322,40.005 41.91,40.005 38.735,41.593 40.322,41.593 41.91,41.593 38.735,43.18 40.322,43.18 41.91,43.18 38.735,44.767 40.322,44.767 41.91,44.767 38.735,46.355 40.322,46.355 41.91,46.355
NetD1002_2: D1002.2 Q1000.3 U1001.6 | length 17
  Top Layer w0.635: v1(27.94,36.195) 33.337,36.195 v2(34.29,35.242) ; Q1000.3@28.892,39.052 Q1000.3
  Top Layer w1.27: v1(27.94,36.195) 27.94,38.1 Q1000.3@28.892,39.052
  Bottom Layer w0.635: v1(27.94,36.195) 27.94,35.242 28.575,34.608 U1001.6 ; v2(34.29,35.242) 35.828,35.242 D1002.2
NetD1003_1: D1003.1 R1007.2 T1000.5 | length 47.8
  Top Layer w1.27: 52.905,33.972 52.905,40.005 53.948,41.047 T1000.5
  Bottom Layer w1.016: R1007.2@32.385,22.86 50.482,22.86 ; 50.8,23.177 53.023,25.4 53.023,40.322 53.747,41.047 T1000.5
NetD1003_3: D1003.3 R1009.2 | length 2.5
  Top Layer w1.27: D1003.3 55.175,31.249 R1009.2
NetF1_2: 
NetL5_V1_2: 
NetL5_V2_2: 
NetL5_V3_2: 
NetQ2_1: 
NetQ2_3: 
NetQ1000_1: Q1000.1 R1012.1 | length 3.9
  Top Layer w1.27: R1012.1 29.882,44.196 Q1000.1
NetQ1001_4: Q1001.4 R1018.2 R1020.2 | length 8
  Top Layer w0.762: R1020.2@86.042,48.26 86.055,48.272 86.055,49.847 86.042,49.847 86.042,50.165 86.201,50.006 v1(91.043,50.006)
  Bottom Layer w0.762: v1@91.043,50.086 R1018.2@92.011,50.086
NetR1_2: 
NetR3_2: 
NetR4_2: 
NetR5_2: 
NetR12_V1_2: 
NetR12_V2_2: 
NetR12_V3_2: 
NetR13_V1_2: 
NetR13_V2_2: 
NetR13_V3_2: 
NetR16_1: 
NetR20_2: 
NetR21_1: 
NetR1002_1: R1002.1 R1004.2 | length 2.1
  Bottom Layer w1.016: R1004.2 R1002.1
NetR1004_1: R1004.1 R1005.2 | length 2.1
  Bottom Layer w1.016: R1005.2 R1004.1
NetR1007_1: R1007.1 R1015.2 U1001.2 | length 4.6
  Bottom Layer w0.635: U1001.2 29.845,26.188 30.633,25.4 ; R1007.1 R1015.2
NetR1011_1: R1011.1 R1016.2 U1000.2 | length 4.8
  Bottom Layer w0.305: U1000.2@94.688,45.879 95.567,45.879 95.885,45.561 R1011.1@95.885,44.053
  Bottom Layer w0.635: R1016.2@92.71,46.038 R1016.2 U1000.2
NetR1013_2: R1013.2 U1001.3 | length 2.5
  Bottom Layer w0.635: R1013.2 U1001.3
NetR1014_2: R1014.2 U1001.4 | length 2.6
  Bottom Layer w0.635: R1014.2 26.67,26.67 ; 26.987,26.67 27.305,26.987 U1001.4
NetR1017_2: R1017.2 U1000.3 | length 1.8
  Bottom Layer w0.635: R1017.2@93.027,47.307 94.365,47.307 U1000.3
NetR1018_1: R1018.1 U1000.4 | length 4.9
  Bottom Layer w0.635: R1018.1@94.456,49.847 95.885,49.847 97.085,48.647 U1000.4 U1000.4@97.152,46.987
NetR1021_2: R1021.2 R1022.2 R1023.2 R1024.2 TP1004.1 | length 22.2
  Top Layer w1.016: v1(82.233,29.21) 82.233,27.94 83.502,26.67 89.218,26.67 90.487,27.94 TP1004.1
  Bottom Layer w1.016: R1023.2 82.233,30.48 v1(82.233,29.21) ; R1022.2@88.9,33.655 R1022.2 90.487,33.655 ; TP1004.1 90.487,33.655 ; R1021.2@91.757,33.655 90.487,33.655
NetR1023_1: R1023.1 U1002.1 | length 12.2
  Bottom Layer w0.762: U1002.1 78.422,28.575 78.74,28.892 R1023.1@78.74,30.162
NetR1026_2: R1026.2 U1002.3 | length 33.4
  Top Layer w1.016: R1026.2@34.608,22.86 57.785,22.86 58.42,23.495 58.42,30.797 58.737,31.115 U1002.3
NetT1_1: 
NetT1_3: 
NetTP18_1: 
PGND: C1001.2 C1002.2 C1010.2 C1012.2 C1013.2 C1017.2 C1018.2 D1000.4 D1004.2 R1013.1 R1014.1 R1015.1 R1027.1 T1000.4 U1001.7 | length 184.6
  Top Layer w1.27: v1(40.322,27.305) C1010.2 43.255,29.678 48.336,34.759 48.336,41.649 50.225,43.537 T1000.4
  Top Layer w2.54: D1000.4 5.39,46.792 C1002.2 16.887,46.792 C1001.2
  Bottom Layer w0.635: 25.082,24.13 25.082,29.527 ; 25.4,24.13 26.035,23.495 ; 25.4,29.527 26.035,30.162 29.21,30.162 29.845,30.797 ; 25.87,23.495 R1013.1@28.258,23.495 ; 29.21,39.37 29.21,37.465 29.845,36.83 U1001.7 29.845,30.797 ; C1012.2 38.481,30.416 40.322,28.575 v1(40.322,27.305) ; C1017.2@34.925,28.422 34.925,29.527 34.29,30.162 30.48,30.162 29.845,30.797
  Bottom Layer w0.762: R1015.1@32.703,24.765 48.895,24.765 50.8,26.67 ; 34.925,25.4 C1017.2@34.925,28.422
  Bottom Layer w1.27: C1001.2@29.21,59.055 31.115,60.96 53.975,60.96 55.245,62.23 C1018.2 ; 50.8,26.67 50.8,41.275 53.062,43.537 T1000.4
  Bottom Layer w2.54: 29.21,39.37 C1001.2@29.21,59.055
RS1_N: 
RS1_P: 
RS_N: 
RS_P: 
V_L1: F1000.2 | length 5.4
  Top Layer w1.778: F1000.2 35.56,15.557 39,15
V_L2: 
V_L3: 
V_N: RT1000.1 | length 5.4
  Top Layer w1.778: 5.294,16.931 8,15
  Top Layer w2.54: RT1000.1 5.294,16.931
V_PAHSE1: 
V_PAHSE2: 
V_PAHSE3: 
V_PAHSE_N: 
pads on no net: D1003.2 Designator9.1@8,15 Designator9.1@40,15 Designator9.1@108,70 T1000.2 T1000.6 T1000.7 T1000.14

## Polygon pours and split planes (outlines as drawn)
NetD1001_2 on Top Layer "Top Layer-No Net" (solid, remove dead copper, pour order 31): 35.56,38.735 47.625,38.735 47.625,49.847 35.56,49.847
NetC1014_1 on Top Layer "Top Layer-No Net 1" (solid, remove dead copper, pour order 34): 76.882,51.752 89.852,51.752 89.852,64.453 76.803,64.452
NetC1000_1 on Top Layer "Top Layer-No Net 2" (solid, remove dead copper, pour order 36): 56.197,56.197 44.45,56.197 44.45,61.595 38.417,61.595 38.417,67.31 45.72,67.31
GND on Top Layer "Top Layer-No Net 3" (solid, remove dead copper, pour order 23): 80.01,50.8 95.25,50.8 95.25,42.862 80.01,42.862
NetC1014_1 on Top Layer "Top Layer-No Net 4" (solid, remove dead copper, pour order 29): 74.454,46.514 78.422,46.514 78.422,52.864 74.454,52.864
+9V on Top Layer "Top Layer-No Net 5" (solid, remove dead copper, pour order 32): 74.374,45.561 77.391,45.561 77.47,45.482 77.47,41.91 92.472,41.91 102.711,41.91 102.711,34.29 74.374,34.29
PGND on Bottom Layer "Bottom Layer-No Net 3" (solid, remove dead copper, pour order 38): 20.955,33.972 33.337,33.972 33.972,33.337 33.972,20.32 20.955,20.32
PGND on Bottom Layer "Bottom Layer-No Net 2" (solid, remove dead copper, pour order 37): 55.88,20.32 27.622,20.32 27.622,61.912 55.88,61.912
NetD1001_2 on Bottom Layer "Bottom Layer-No Net" (solid, remove dead copper, pour order 24): 38.1,57.15 46.672,57.15 46.672,37.465 38.1,37.465
NetC1014_1 on Bottom Layer "Bottom Layer-No Net 1" (solid, remove dead copper, pour order 35): 75.248,51.87 75.247,60.96 86.997,60.96 87.002,51.87
GND on Bottom Layer "Bottom Layer-No Net 4" (solid, remove dead copper, pour order 26): 76.756,50.8 87.947,50.8 87.947,63.817 106.68,63.817 106.68,27.94 76.756,27.94

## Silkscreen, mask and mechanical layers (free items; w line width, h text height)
Top Overlay:
  text "PMP10145_RevA" at 46.672,17.145 h1.27
Bottom Overlay:
  lines w0.152: 109.474,25.654 112.776,25.654
Mechanical 1:
  the board outline again, w0.254
Mechanical 15:
  text "DC 9V ->" at 87.122,58.928 h2.54
  text "DC GND->" at 92.583,51.181 h2.54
